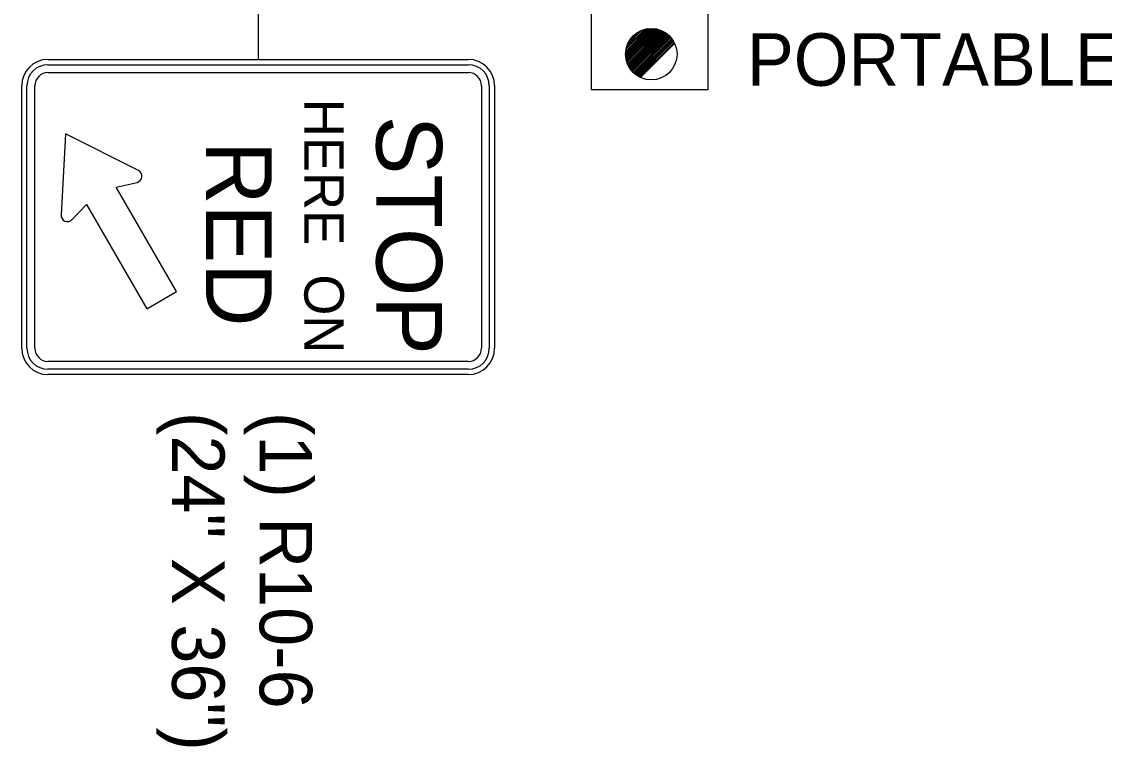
# Model space of a CAD drawing. Extents: x 1925873 to 1930787, y 596452 to 599617.
# Drawn here: x 1926188.1 to 1926311.8, y 597308.7 to 597391.5 of the extents above; entities that cross this region are included whole.
import ezdxf

# ---------------------------------------------------------------- set-up
doc = ezdxf.new("R2010")
doc.units = 0
for name, color, linetype in [('Default', 7, 'Continuous'), ('P_TC_Signs_Permanent', 7, 'Continuous'), ('R_Border', 7, 'Continuous')]:
    doc.layers.add(name, color=color, linetype=linetype)

msp = doc.modelspace()

# ---------------------------------------------------------------- linework, layer by layer
at = {"layer": 'Default'}
for p, q in [((1926257.08, 597387.71), (1926260.06, 597390.69)), ((1926257.08, 597387.89), (1926259.87, 597390.69)), ((1926257.09, 597387.54), (1926260.23, 597390.68)), ((1926257.1, 597387.37), (1926260.4, 597390.67)), ((1926257.1, 597388.09), (1926259.68, 597390.67)), ((1926257.13, 597387.22), (1926260.55, 597390.64)), ((1926257.13, 597388.31), (1926259.46, 597390.64)), ((1926257.16, 597387.07), (1926260.7, 597390.61)), ((1926257.19, 597388.54), (1926259.23, 597390.58)), ((1926257.2, 597386.92), (1926260.85, 597390.57)), ((1926257.24, 597386.79), (1926260.98, 597390.53)), ((1926257.28, 597388.81), (1926258.95, 597390.49)), ((1926257.29, 597386.65), (1926261.11, 597390.48)), ((1926257.34, 597386.53), (1926261.24, 597390.42)), ((1926257.4, 597386.41), (1926261.36, 597390.37)), ((1926257.44, 597389.15), (1926258.62, 597390.33)), ((1926257.47, 597386.29), (1926261.48, 597390.3)), ((1926257.53, 597386.18), (1926261.59, 597390.23)), ((1926257.61, 597386.07), (1926261.7, 597390.16)), ((1926257.68, 597385.96), (1926261.81, 597390.09)), ((1926257.76, 597385.86), (1926261.91, 597390.01)), ((1926257.85, 597385.76), (1926262, 597389.92)), ((1926257.94, 597385.67), (1926262.1, 597389.83)), ((1926258.03, 597385.58), (1926262.18, 597389.74)), ((1926258.12, 597385.5), (1926262.27, 597389.64)), ((1926258.22, 597385.42), (1926262.35, 597389.54)), ((1926258.33, 597385.34), (1926262.43, 597389.44)), ((1926258.44, 597385.27), (1926262.5, 597389.33)), ((1926258.55, 597385.2), (1926262.57, 597389.22)), ((1926258.67, 597385.14), (1926262.63, 597389.1)), ((1926258.79, 597385.08), (1926262.69, 597388.98))]:
    msp.add_line(p, q, dxfattribs=at)
msp.add_lwpolyline([(1926253.18, 597408.2), (1926266.47, 597408.2), (1926266.47, 597383.66), (1926253.18, 597383.66)], close=True, dxfattribs=at)
msp.add_circle((1926260.02, 597387.75), 2.94, dxfattribs=at)
at = {"layer": 'P_TC_Signs_Permanent'}
for p, q in [((1926191.12, 597387.15), (1926239.12, 597387.15)), ((1926191.12, 597386.55), (1926239.12, 597386.55)), ((1926191.12, 597385.65), (1926239.12, 597385.65)), ((1926188.12, 597354.15), (1926188.12, 597384.15)), ((1926188.72, 597354.15), (1926188.72, 597384.15)), ((1926189.62, 597354.15), (1926189.62, 597384.15)), ((1926240.62, 597384.15), (1926240.62, 597354.15)), ((1926241.52, 597384.15), (1926241.52, 597354.15)), ((1926242.12, 597384.15), (1926242.12, 597354.15)), ((1926239.12, 597352.65), (1926191.12, 597352.65)), ((1926239.12, 597351.75), (1926191.12, 597351.75)), ((1926239.12, 597351.15), (1926191.12, 597351.15))]:
    msp.add_line(p, q, dxfattribs=at)
for points in [[(1926201.45, 597374.45), (1926193.13, 597378.65), (1926192.62, 597369.38)], [(1926193.86, 597368.84), (1926195.51, 597370.59), (1926202.4, 597358.66), (1926205.81, 597360.63), (1926198.92, 597372.56), (1926201.29, 597373.1)]]:
    msp.add_lwpolyline(points, dxfattribs=at)
for centre, radius, start, end in [((1926191.12, 597384.15), 3, 90, 180), ((1926239.12, 597384.15), 3, 360, 90), ((1926191.12, 597384.15), 2.4, 90, 180), ((1926191.12, 597384.15), 1.5, 90, 180), ((1926239.12, 597384.15), 2.4, 360, 90), ((1926239.12, 597384.15), 1.5, 360, 90), ((1926201.13, 597373.81), 0.72, 283.0349, 63.2286), ((1926193.34, 597369.34), 0.72, 176.857, 316.6377), ((1926191.12, 597354.15), 3, 180, 270), ((1926191.12, 597354.15), 2.4, 180, 270), ((1926191.12, 597354.15), 1.5, 180, 270), ((1926239.12, 597354.15), 3, 270, 360), ((1926239.12, 597354.15), 2.4, 270, 360), ((1926239.12, 597354.15), 1.5, 270, 360)]:
    msp.add_arc(centre, radius, start, end, dxfattribs=at)
at = {"layer": 'R_Border'}
msp.add_line((1926215.12, 597404.17), (1926215.12, 597387.15), dxfattribs=at)

# ---------------------------------------------------------------- texts
at = {"layer": 'Default'}
msp.add_text('PORTABLE TRAFFIC SIGNAL SYSTEM', height=6, rotation=360, dxfattribs=at).set_placement((1926270.94, 597384.14))
at = {"layer": 'P_TC_Signs_Permanent'}
for s, height, p in [('HERE  ON', 4.5, (1926220.4, 597382.65)), ('STOP', 7.5, (1926228.62, 597380.71)), ('RED', 7.5, (1926209.18, 597377.82))]:
    msp.add_text(s, height=height, rotation=270, dxfattribs=at).set_placement(p)
at = {"layer": 'R_Border'}
for s, height, p in [('(24" X 36")', 5.9996, (1926205.29, 597346.87)), ('(1) R10-6', 6, (1926215.29, 597346.87))]:
    msp.add_text(s, height=height, rotation=270, dxfattribs=at).set_placement(p)

doc.saveas('drawing.dxf')
